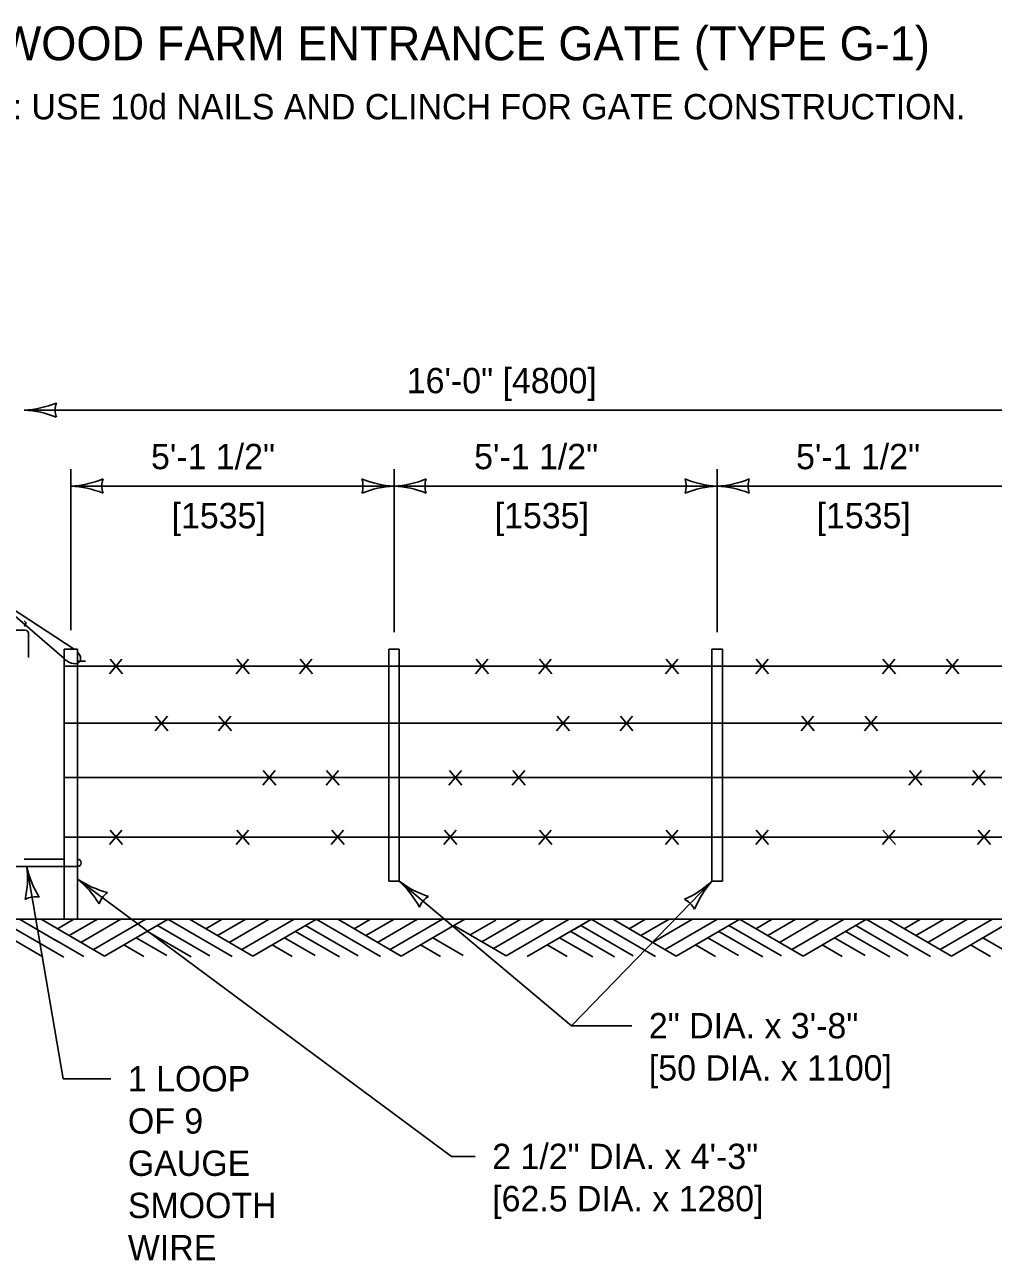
# Model space of a CAD drawing. Extents: x 49991.4 to 50021, y 49987.6 to 50011.4.
# Drawn here: x 50003.336 to 50005.629, y 50005.27 to 50008.197 of the extents above; entities that cross this region are included whole.
import ezdxf

# ---------------------------------------------------------------- set-up
doc = ezdxf.new("R2010")
doc.units = 0
for name, color, linetype in [('Level 1', 7, 'Continuous'), ('Level 2', 7, 'Continuous'), ('Level 3', 7, 'Continuous')]:
    doc.layers.add(name, color=color, linetype=linetype)

msp = doc.modelspace()

# ---------------------------------------------------------------- linework, layer by layer
at = {"layer": 'Level 1'}
for p, q in [((50003.4298, 50006.6948), (50003.2786, 50006.8253)), ((50003.4528, 50006.7176), (50003.3022, 50006.8158)), ((50003.3375, 50006.7817), (50003.3346, 50006.7845)), ((50003.3346, 50006.7716), (50003.3376, 50006.7745)), ((50003.3374, 50006.7623), (50003.2574, 50006.7623)), ((50003.3449, 50006.6972), (50003.3449, 50006.7548)), ((50003.461, 50006.7176), (50003.4298, 50006.7176)), ((50003.4298, 50006.7176), (50003.4298, 50006.663)), ((50003.461, 50006.7176), (50003.461, 50006.6638)), ((50004.1979, 50006.7176), (50004.1979, 50006.1676)), ((50004.2229, 50006.7176), (50004.1979, 50006.7176)), ((50004.2229, 50006.7176), (50004.2229, 50006.1676)), ((50004.9629, 50006.7176), (50004.9629, 50006.1676)), ((50004.9879, 50006.7176), (50004.9629, 50006.7176)), ((50004.9879, 50006.7176), (50004.9879, 50006.1676)), ((50003.4298, 50006.6773), (50005.6786, 50006.6773)), ((50003.461, 50006.6889), (50003.48, 50006.6889)), ((50003.5367, 50006.6592), (50003.5661, 50006.6939)), ((50003.5674, 50006.6592), (50003.5381, 50006.6939)), ((50003.8367, 50006.6592), (50003.8661, 50006.6939)), ((50003.8674, 50006.6592), (50003.8381, 50006.6939)), ((50003.9867, 50006.6592), (50004.0161, 50006.6939)), ((50004.0174, 50006.6592), (50003.9881, 50006.6939)), ((50004.4034, 50006.6592), (50004.4327, 50006.6939)), ((50004.4341, 50006.6592), (50004.4047, 50006.6939)), ((50004.5534, 50006.6592), (50004.5827, 50006.6939)), ((50004.5841, 50006.6592), (50004.5547, 50006.6939)), ((50004.8534, 50006.6592), (50004.8827, 50006.6939)), ((50004.8841, 50006.6592), (50004.8547, 50006.6939)), ((50005.0667, 50006.6592), (50005.0961, 50006.6939)), ((50005.0974, 50006.6592), (50005.0681, 50006.6939)), ((50005.3667, 50006.6592), (50005.3961, 50006.6939)), ((50005.3974, 50006.6592), (50005.3681, 50006.6939)), ((50005.5167, 50006.6592), (50005.5461, 50006.6939)), ((50005.5474, 50006.6592), (50005.5181, 50006.6939)), ((50003.4298, 50006.663), (50003.4298, 50006.0776)), ((50003.461, 50006.6638), (50003.461, 50006.0776)), ((50003.4298, 50006.5423), (50005.6786, 50006.5423)), ((50003.6446, 50006.5242), (50003.6739, 50006.5589)), ((50003.6753, 50006.5242), (50003.6459, 50006.5589)), ((50003.7946, 50006.5242), (50003.8239, 50006.5589)), ((50003.8253, 50006.5242), (50003.7959, 50006.5589)), ((50004.5955, 50006.5242), (50004.6249, 50006.5589)), ((50004.6262, 50006.5242), (50004.5969, 50006.5589)), ((50004.7455, 50006.5242), (50004.7749, 50006.5589)), ((50004.7762, 50006.5242), (50004.7469, 50006.5589)), ((50005.1746, 50006.5242), (50005.2039, 50006.5589)), ((50005.2053, 50006.5242), (50005.1759, 50006.5589)), ((50005.3246, 50006.5242), (50005.3539, 50006.5589)), ((50005.3553, 50006.5242), (50005.3259, 50006.5589)), ((50003.4298, 50006.4133), (50005.6786, 50006.4133)), ((50003.8996, 50006.3952), (50003.9289, 50006.4299)), ((50003.9303, 50006.3952), (50003.9009, 50006.4299)), ((50004.0496, 50006.3952), (50004.0789, 50006.4299)), ((50004.0803, 50006.3952), (50004.0509, 50006.4299)), ((50004.3405, 50006.3952), (50004.3699, 50006.4299)), ((50004.3712, 50006.3952), (50004.3419, 50006.4299)), ((50004.4905, 50006.3952), (50004.5199, 50006.4299)), ((50004.5212, 50006.3952), (50004.4919, 50006.4299)), ((50005.4296, 50006.3952), (50005.4589, 50006.4299)), ((50005.4603, 50006.3952), (50005.4309, 50006.4299)), ((50005.5796, 50006.3952), (50005.6089, 50006.4299)), ((50005.6103, 50006.3952), (50005.5809, 50006.4299)), ((50003.4298, 50006.2723), (50005.6786, 50006.2723)), ((50003.5367, 50006.2542), (50003.5661, 50006.2889)), ((50003.5674, 50006.2542), (50003.5381, 50006.2889)), ((50003.8367, 50006.2542), (50003.8661, 50006.2889)), ((50003.8674, 50006.2542), (50003.8381, 50006.2889)), ((50004.0617, 50006.2542), (50004.0911, 50006.2889)), ((50004.0924, 50006.2542), (50004.0631, 50006.2889)), ((50004.3284, 50006.2542), (50004.3577, 50006.2889)), ((50004.3591, 50006.2542), (50004.3297, 50006.2889)), ((50004.5534, 50006.2542), (50004.5827, 50006.2889)), ((50004.5841, 50006.2542), (50004.5547, 50006.2889)), ((50004.8534, 50006.2542), (50004.8827, 50006.2889)), ((50004.8841, 50006.2542), (50004.8547, 50006.2889)), ((50005.0667, 50006.2542), (50005.0961, 50006.2889)), ((50005.0974, 50006.2542), (50005.0681, 50006.2889)), ((50005.3667, 50006.2542), (50005.3961, 50006.2889)), ((50005.3974, 50006.2542), (50005.3681, 50006.2889)), ((50005.5917, 50006.2542), (50005.6211, 50006.2889)), ((50005.6224, 50006.2542), (50005.5931, 50006.2889)), ((50003.3349, 50006.2199), (50003.4298, 50006.2199)), ((50003.2599, 50006.2023), (50003.461, 50006.2023)), ((50004.2229, 50006.1676), (50004.1979, 50006.1676)), ((50004.9879, 50006.1676), (50004.9629, 50006.1676)), ((50001.4073, 50006.0773), (50003.3634, 50006.0773)), ((50003.299, 50006.0624), (50003.4286, 50005.9875)), ((50003.3239, 50006.0773), (50003.4155, 50006.0243)), ((50003.3349, 50006.0773), (50007.5434, 50006.0773)), ((50003.3749, 50006.0773), (50003.5253, 50005.9904)), ((50003.4524, 50006.0773), (50003.4136, 50006.0549)), ((50003.43, 50006.0776), (50003.461, 50006.0776)), ((50003.5085, 50006.0773), (50003.4416, 50006.0388)), ((50003.5637, 50006.0773), (50003.4693, 50006.0228)), ((50003.6228, 50006.0773), (50003.4989, 50006.0057)), ((50003.6758, 50006.0773), (50003.5253, 50005.9904)), ((50003.6501, 50006.0624), (50003.7744, 50005.9906)), ((50003.675, 50006.0773), (50003.8272, 50005.9894)), ((50003.726, 50006.0773), (50003.8765, 50005.9904)), ((50003.8035, 50006.0773), (50003.7648, 50006.0549)), ((50003.8596, 50006.0773), (50003.7927, 50006.0388)), ((50003.9148, 50006.0773), (50003.8204, 50006.0228)), ((50003.9739, 50006.0773), (50003.85, 50006.0057)), ((50004.0269, 50006.0773), (50003.8765, 50005.9904)), ((50004.0012, 50006.0624), (50004.1255, 50005.9906)), ((50004.0261, 50006.0773), (50004.1783, 50005.9894)), ((50004.0771, 50006.0773), (50004.2276, 50005.9904)), ((50004.1546, 50006.0773), (50004.1159, 50006.0549)), ((50004.2107, 50006.0773), (50004.1438, 50006.0388)), ((50004.2659, 50006.0773), (50004.1715, 50006.0228)), ((50004.325, 50006.0773), (50004.2011, 50006.0057)), ((50004.3523, 50006.0624), (50004.2276, 50005.9904)), ((50004.378, 50006.0773), (50004.3466, 50006.0592)), ((50004.3522, 50006.0624), (50004.4758, 50005.991)), ((50004.4518, 50006.0756), (50004.3906, 50006.0403)), ((50004.5108, 50006.0773), (50004.4185, 50006.0241)), ((50004.566, 50006.0773), (50004.4462, 50006.0081)), ((50004.6251, 50006.0773), (50004.4758, 50005.991)), ((50004.6782, 50006.0773), (50004.5259, 50005.9894)), ((50004.6781, 50006.0773), (50004.6367, 50006.0535)), ((50004.6524, 50006.0624), (50004.7767, 50005.9906)), ((50004.6773, 50006.0773), (50004.8295, 50005.9894)), ((50004.7283, 50006.0773), (50004.8788, 50005.9904)), ((50004.8058, 50006.0773), (50004.7671, 50006.0549)), ((50004.8619, 50006.0773), (50004.795, 50006.0388)), ((50004.9171, 50006.0773), (50004.8227, 50006.0228)), ((50004.9762, 50006.0773), (50004.8523, 50006.0057)), ((50005.0292, 50006.0773), (50004.8788, 50005.9904)), ((50005.0035, 50006.0624), (50005.1278, 50005.9906)), ((50005.0284, 50006.0773), (50005.1789, 50005.9904)), ((50005.1059, 50006.0773), (50005.0672, 50006.0549)), ((50005.162, 50006.0773), (50005.0951, 50006.0388)), ((50005.2172, 50006.0773), (50005.1228, 50006.0228)), ((50005.2763, 50006.0773), (50005.1524, 50006.0057)), ((50005.3293, 50006.0773), (50005.1789, 50005.9904)), ((50005.3036, 50006.0624), (50005.4279, 50005.9906)), ((50005.3285, 50006.0773), (50005.4807, 50005.9894)), ((50005.3795, 50006.0773), (50005.53, 50005.9904)), ((50005.457, 50006.0773), (50005.4183, 50006.0549)), ((50005.5131, 50006.0773), (50005.4462, 50006.0388)), ((50005.5683, 50006.0773), (50005.4739, 50006.0228)), ((50005.6274, 50006.0773), (50005.5035, 50006.0057)), ((50005.6804, 50006.0773), (50005.53, 50005.9904)), ((50003.2753, 50006.0488), (50003.3793, 50005.9887)), ((50003.6001, 50006.0336), (50003.6723, 50005.9918)), ((50003.6264, 50006.0488), (50003.7304, 50005.9887)), ((50003.9512, 50006.0336), (50004.0234, 50005.9918)), ((50003.9775, 50006.0488), (50004.0815, 50005.9887)), ((50004.3023, 50006.0335), (50004.3745, 50005.9918)), ((50004.6024, 50006.0335), (50004.6809, 50005.9882)), ((50004.6287, 50006.0487), (50004.7327, 50005.9887)), ((50004.9535, 50006.0336), (50005.0257, 50005.9918)), ((50004.9798, 50006.0488), (50005.0838, 50005.9887)), ((50005.2536, 50006.0336), (50005.3258, 50005.9918)), ((50005.2799, 50006.0488), (50005.3839, 50005.9887)), ((50005.6047, 50006.0336), (50005.6769, 50005.9918)), ((50003.4069, 50006.0294), (50003.4761, 50005.9894)), ((50003.5708, 50006.0167), (50003.6179, 50005.9894)), ((50003.9219, 50006.0167), (50003.969, 50005.9894)), ((50004.2733, 50006.0165), (50004.3201, 50005.9894)), ((50004.5731, 50006.0167), (50004.6202, 50005.9894)), ((50004.9242, 50006.0167), (50004.9713, 50005.9894)), ((50005.2243, 50006.0167), (50005.2714, 50005.9894)), ((50005.5754, 50006.0167), (50005.6225, 50005.9894))]:
    msp.add_line(p, q, dxfattribs=at)
for centre, radius, start, end in [((50003.334, 50006.7781), 0.005, 314.5626, 45.8814), ((50003.3374, 50006.7548), 0.0075, 0, 90), ((50003.461, 50006.2111), 0.0088, 270, 90)]:
    msp.add_arc(centre, radius, start, end, dxfattribs=at)
for start_param, end_param in [(4.447373, 7.509495), (1.635161, 1.646974)]:
    msp.add_ellipse((50003.4447, 50006.7034), major_axis=(0.0218, -0.0157), ratio=0.605681, start_param=start_param, end_param=end_param, dxfattribs=at)
at = {"layer": 'Level 3'}
for p, q in [((50003.3349, 50007.2836), (50005.7348, 50007.2836)), ((50003.4454, 50006.7624), (50003.4454, 50007.1436)), ((50004.2104, 50006.7576), (50004.2104, 50007.1436)), ((50004.9754, 50006.7576), (50004.9754, 50007.1436)), ((50003.4454, 50007.1036), (50004.2104, 50007.1036)), ((50004.2104, 50007.1036), (50004.9754, 50007.1036)), ((50004.9754, 50007.1036), (50005.7348, 50007.1036)), ((50003.3409, 50006.2023), (50003.4269, 50005.6996)), ((50003.461, 50006.1728), (50004.3462, 50005.5157)), ((50004.2229, 50006.1676), (50004.631, 50005.8254)), ((50004.631, 50005.8254), (50004.9629, 50006.1676)), ((50004.631, 50005.8254), (50004.7738, 50005.8254)), ((50003.4269, 50005.6996), (50003.5403, 50005.6996)), ((50004.3462, 50005.5157), (50004.4029, 50005.5157))]:
    msp.add_line(p, q, dxfattribs=at)
for centre, radius, start, end in [((50003.3234, 50007.5163), 0.233, 272.8273, 292.0772), ((50003.4631, 50007.2836), 0.0548, 162.1388, 197.8612), ((50003.3257, 50007.0615), 0.2223, 67.456, 87.6395), ((50003.4339, 50007.3363), 0.233, 272.8273, 292.0772), ((50003.5736, 50007.1036), 0.0548, 162.1388, 197.8612), ((50004.2196, 50007.3257), 0.2223, 247.456, 267.6395), ((50004.0822, 50007.1036), 0.0548, 342.1388, 17.8612), ((50004.1989, 50007.3363), 0.233, 272.8273, 292.0772), ((50004.3386, 50007.1036), 0.0548, 162.1388, 197.8612), ((50004.9846, 50007.3257), 0.2223, 247.456, 267.6395), ((50004.8472, 50007.1036), 0.0548, 342.1388, 17.8612), ((50004.9639, 50007.3363), 0.233, 272.8273, 292.0772), ((50005.1036, 50007.1036), 0.0548, 162.1388, 197.8612), ((50003.4362, 50006.8815), 0.2223, 67.456, 87.6395), ((50004.2219, 50006.8709), 0.233, 92.8273, 112.0772), ((50004.2012, 50006.8815), 0.2223, 67.456, 87.6395), ((50004.9869, 50006.8709), 0.233, 92.8273, 112.0772), ((50004.9662, 50006.8815), 0.2223, 67.456, 87.6395), ((50003.1204, 50006.1739), 0.2223, 347.1581, 7.3416), ((50003.5684, 50006.2528), 0.233, 192.5294, 211.7792), ((50003.3212, 50005.9999), 0.2223, 30.8684, 51.0519), ((50003.5905, 50006.3665), 0.233, 236.2397, 255.4895), ((50004.0732, 50006.0033), 0.2223, 27.479, 47.6625), ((50004.3636, 50006.3533), 0.233, 232.8503, 252.1001), ((50004.8098, 50006.3288), 0.2223, 293.3357, 313.5192), ((50005.138, 50006.0138), 0.233, 138.707, 157.9569), ((50003.3626, 50006.0759), 0.0548, 81.8409, 117.5632), ((50003.5639, 50006.0964), 0.0548, 125.5512, 161.2735), ((50004.3212, 50006.0852), 0.0548, 122.1618, 157.8841), ((50004.8736, 50006.0756), 0.0548, 28.0185, 63.7409)]:
    msp.add_arc(centre, radius, start, end, dxfattribs=at)

# ---------------------------------------------------------------- texts
at = {"layer": 'Level 2'}
for s, height, p in [('WOOD FARM ENTRANCE GATE (TYPE G-1)', 0.08, (50003.2742, 50008.1123)), ('NOTE: USE 10d NAILS AND CLINCH FOR GATE CONSTRUCTION.', 0.06, (50003.0845, 50007.9723)), ('16\'-0" [4800]', 0.06, (50004.2407, 50007.3236)), ('5\'-1 1/2"', 0.06, (50003.6351, 50007.1436)), ('5\'-1 1/2"', 0.06, (50004.4001, 50007.1436)), ('5\'-1 1/2"', 0.06, (50005.1623, 50007.1436)), ('[1535]', 0.06, (50003.6838, 50007.0036)), ('[1535]', 0.06, (50004.4488, 50007.0036)), ('[1535]', 0.06, (50005.2108, 50007.0036)), ('2" DIA. x 3\'-8"', 0.06, (50004.8138, 50005.7954)), ('[50 DIA. x 1100]', 0.06, (50004.8138, 50005.6954)), ('1 LOOP', 0.06, (50003.5803, 50005.6696)), ('OF 9', 0.06, (50003.5803, 50005.5696)), ('2 1/2" DIA. x 4\'-3"', 0.06, (50004.4429, 50005.4857)), ('GAUGE', 0.06, (50003.5803, 50005.4696)), ('[62.5 DIA. x 1280]', 0.06, (50004.4429, 50005.3857)), ('SMOOTH', 0.06, (50003.5803, 50005.3696)), ('WIRE', 0.06, (50003.5803, 50005.2696))]:
    msp.add_text(s, height=height, dxfattribs=at).set_placement(p)

doc.saveas('drawing.dxf')
